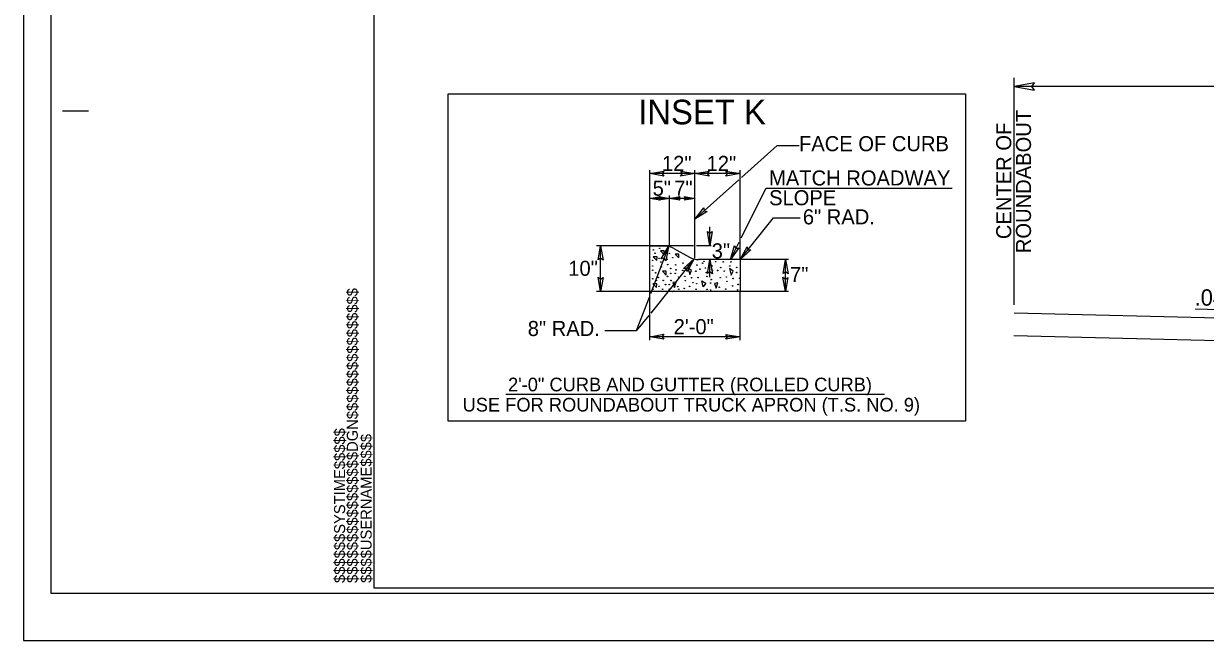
# Model space of a CAD drawing. Extents: x 958711 to 962106, y 831169 to 840840.
# Drawn here: x 958711 to 959274, y 836067 to 836361 of the extents above; entities that cross this region are included whole.
import ezdxf

# ---------------------------------------------------------------- set-up
doc = ezdxf.new("R2010")
doc.units = 0
for name, color, linetype in [('Old_Level_1', 7, 'Continuous'), ('Old_Level_11', 7, 'Continuous'), ('Prop Dimension Text', 7, 'Continuous'), ('Prop Terminator CELL', 7, 'Continuous'), ('Sheet Plot Border Inside CELL', 7, 'Continuous'), ('Sheet Plot Border Outside CELL', 7, 'Continuous'), ('Sheet Typical CELL', 7, 'Continuous'), ('Typical Curb CELL', 7, 'Continuous')]:
    doc.layers.add(name, color=color, linetype=linetype)

msp = doc.modelspace()

# ---------------------------------------------------------------- linework, layer by layer
at = {"layer": 'Old_Level_1'}
for p, q in [((959183.14, 836226.71), (959183.14, 836334.93)), ((959409.36, 836330.79), (959183.14, 836330.79)), ((959053.02, 836287.36), (959070.08, 836302.63)), ((959070.08, 836302.63), (959080.52, 836302.63)), ((959009.31, 836254.84), (959009.31, 836290.83)), ((959030.85, 836248.96), (959030.85, 836290.83)), ((959052.39, 836248.3), (959052.39, 836290.83)), ((959052.39, 836289.22), (959009.31, 836289.22)), ((959030.85, 836267.51), (959051.79, 836286.26)), ((959052.95, 836258.6), (959064.82, 836282.25)), ((959064.82, 836282.25), (959153.53, 836282.25)), ((959018.7, 836277.43), (959009.31, 836277.43)), ((959018.7, 836254.84), (959018.7, 836278.85)), ((959030.85, 836277.43), (959018.7, 836277.43)), ((959052.39, 836248.3), (959068.34, 836268.1)), ((959068.34, 836268.1), (959081.07, 836268.1)), ((959038.01, 836254.84), (959038.01, 836263.83)), ((959047.78, 836248.3), (959051.9, 836256.49)), ((959009.31, 836254.84), (958984, 836254.84)), ((958985.92, 836233.03), (958985.92, 836254.84)), ((959030.17, 836254.84), (959009.31, 836254.84)), ((959018.28, 836254.48), (959009.66, 836231.93)), ((959038.64, 836254.84), (959031.55, 836254.84)), ((959030.56, 836248.54), (959009.79, 836222.78)), ((959038.01, 836239.9), (959038.01, 836248.3)), ((959075.56, 836248.3), (959052.39, 836248.3)), ((959052.39, 836245.6), (959052.39, 836239.13)), ((959074.07, 836233.03), (959074.07, 836248.3)), ((959009.31, 836233.03), (958984, 836233.03)), ((959008.99, 836230.18), (959002.89, 836214.22)), ((959009.31, 836209.88), (959009.31, 836233.03)), ((959052.39, 836209.88), (959052.39, 836233.03)), ((959075.56, 836233.03), (959052.39, 836233.03)), ((959183.14, 836222.88), (959403.98, 836217.36)), ((959269.32, 836224.71), (959300.64, 836224.08)), ((959008.85, 836221.62), (959002.89, 836214.22)), ((959002.89, 836214.22), (958987.87, 836214.22)), ((959052.39, 836211.44), (959009.31, 836211.44)), ((959182.87, 836212.14), (959403.98, 836206.61)), ((958940.77, 836184.02), (959121.19, 836184.02))]:
    msp.add_line(p, q, dxfattribs=at)
msp.add_lwpolyline([(958913.22, 836327.23), (959159.94, 836327.23), (959159.94, 836171.22), (958913.22, 836171.22)], close=True, dxfattribs=at)
at = {"layer": 'Old_Level_11'}
msp.add_lwpolyline([(959192.75, 836332.44), (959183.14, 836330.79), (959192.81, 836329.07), (959191.58, 836330.79)], close=True, dxfattribs=at)
at = {"layer": 'Prop Terminator CELL'}
for points in [[(959016.06, 836288.06), (959009.31, 836289.22), (959016.1, 836290.42), (959015.23, 836289.22)], [(959024.1, 836290.39), (959030.85, 836289.22), (959024.06, 836288.02), (959024.92, 836289.22)], [(959037.6, 836288.06), (959030.85, 836289.22), (959037.64, 836290.42), (959036.77, 836289.22)], [(959045.64, 836290.39), (959052.39, 836289.22), (959045.6, 836288.02), (959046.46, 836289.22)], [(959014.26, 836276.58), (959009.31, 836277.43), (959014.29, 836278.31), (959013.65, 836277.43)], [(959013.75, 836278.29), (959018.7, 836277.43), (959013.73, 836276.55), (959014.36, 836277.43)], [(959023.65, 836276.58), (959018.7, 836277.43), (959023.68, 836278.31), (959023.05, 836277.43)], [(959025.9, 836278.29), (959030.85, 836277.43), (959025.87, 836276.55), (959026.5, 836277.43)], [(959036.65, 836271.15), (959030.85, 836267.51), (959035.1, 836272.93), (959035.26, 836271.46)], [(959039.17, 836261.59), (959038.01, 836254.84), (959036.81, 836261.63), (959038.01, 836260.77)], [(958984.76, 836248.09), (958985.92, 836254.84), (958987.12, 836248.05), (958985.92, 836248.92)], [(959014.78, 836248.59), (959018.28, 836254.48), (959016.98, 836247.71), (959016.16, 836248.94)], [(959051.85, 836253.81), (959047.78, 836248.3), (959049.76, 836254.9), (959050.44, 836253.59)], [(959057.53, 836252.83), (959052.39, 836248.3), (959055.71, 836254.34), (959056.1, 836252.91)], [(959025.41, 836244.02), (959030.56, 836248.54), (959027.23, 836242.51), (959026.84, 836243.93)], [(959036.85, 836241.55), (959038.01, 836248.3), (959039.21, 836241.51), (959038.01, 836242.37)], [(959072.91, 836241.55), (959074.07, 836248.3), (959075.27, 836241.51), (959074.07, 836242.37)], [(958987.08, 836239.78), (958985.92, 836233.03), (958984.72, 836239.82), (958985.92, 836238.96)], [(959075.23, 836239.78), (959074.07, 836233.03), (959072.87, 836239.82), (959074.07, 836238.96)], [(959016.06, 836210.27), (959009.31, 836211.44), (959016.1, 836212.64), (959015.23, 836211.44)], [(959045.64, 836212.6), (959052.39, 836211.44), (959045.6, 836210.24), (959046.46, 836211.44)]]:
    msp.add_lwpolyline(points, close=True, dxfattribs=at)
at = {"layer": 'Sheet Plot Border Inside CELL'}
msp.add_lwpolyline([(960390.3, 837144.29), (958723.8, 837144.29), (958723.8, 836089.19), (960390.3, 836089.19)], close=True, dxfattribs=at)
at = {"layer": 'Sheet Plot Border Outside CELL'}
msp.add_lwpolyline([(960394.8, 837166.74), (958710.8, 837166.74), (958710.8, 836066.74), (960394.8, 836066.74)], close=True, dxfattribs=at)
at = {"layer": 'Sheet Typical CELL'}
for p, q in [((958729.3, 836319.24), (958741.8, 836319.24)), ((958877.8, 836091.74), (958877.8, 836091.74)), ((958877.8, 836091.74), (958877.8, 836091.74)), ((958877.8, 836091.74), (958877.8, 836091.74)), ((958877.8, 836091.74), (958877.8, 836091.74)), ((958877.8, 836091.74), (958877.8, 836091.74)), ((958877.8, 836091.74), (958877.8, 836091.74))]:
    msp.add_line(p, q, dxfattribs=at)
msp.add_lwpolyline([(960377.8, 837141.74), (958877.8, 837141.74), (958877.8, 836091.74), (960377.8, 836091.74)], close=True, dxfattribs=at)
msp.add_lwpolyline([(958915.3, 836091.74), (958915.3, 836091.74)], dxfattribs=at)
at = {"layer": 'Typical Curb CELL'}
for p, q in [((959009.31, 836233.03), (959009.31, 836254.84)), ((959009.31, 836254.84), (959016.69, 836254.66)), ((959016.25, 836252.36), (959014.4, 836252.36)), ((959014.4, 836252.36), (959016.15, 836250.51)), ((959016.15, 836250.51), (959016.25, 836252.36)), ((959020.81, 836253.54), (959028.3, 836249.42)), ((959023.25, 836250.87), (959021.39, 836250.87)), ((959021.39, 836250.87), (959023.14, 836249.02)), ((959023.14, 836249.02), (959023.25, 836250.87)), ((959012.86, 836249.62), (959011.01, 836249.62)), ((959011.01, 836249.62), (959012.76, 836247.76)), ((959012.76, 836247.76), (959012.86, 836249.62)), ((959052.39, 836248.3), (959032.64, 836248.3)), ((959052.39, 836248.3), (959052.39, 836233.03)), ((959017.22, 836242.67), (959015.37, 836242.67)), ((959015.37, 836242.67), (959017.12, 836240.81)), ((959017.12, 836240.81), (959017.22, 836242.67)), ((959027.51, 836244.35), (959028.41, 836241.13)), ((959029.28, 836243.09), (959027.51, 836244.35)), ((959028.41, 836241.13), (959029.28, 836243.09)), ((959047.32, 836244.01), (959048.21, 836240.81)), ((959049.08, 836242.75), (959047.32, 836244.01)), ((959048.21, 836240.81), (959049.08, 836242.75)), ((959012.7, 836236.77), (959010.85, 836236.77)), ((959010.85, 836236.77), (959012.6, 836234.91)), ((959012.6, 836234.91), (959012.7, 836236.77)), ((959021.97, 836237.55), (959020.41, 836237.25)), ((959020.41, 836237.25), (959021.2, 836234.91)), ((959021.2, 836234.91), (959021.97, 836237.55)), ((959034.14, 836238.13), (959036.08, 836237.06)), ((959034.82, 836235.31), (959034.14, 836238.13)), ((959036.08, 836237.06), (959034.82, 836235.31)), ((959041.77, 836237.21), (959040.22, 836236.91)), ((959040.22, 836236.91), (959041.01, 836234.57)), ((959041.01, 836234.57), (959041.77, 836237.21)), ((959052.39, 836233.03), (959009.31, 836233.03))]:
    msp.add_line(p, q, dxfattribs=at)
for centre, radius in [((959011.06, 836252.86), 0.137), ((959011.89, 836251.29), 0.137), ((959014.1, 836253.6), 0.137), ((959018.26, 836253.6), 0.137), ((959018.67, 836251.25), 0.137), ((959010.73, 836247.88), 0.137), ((959010.73, 836245.2), 0.137), ((959013.83, 836248.84), 0.137), ((959014.61, 836247.09), 0.137), ((959017.61, 836248.43), 0.137), ((959017.89, 836245.89), 0.137), ((959020.29, 836249.17), 0.137), ((959021.69, 836245.71), 0.137), ((959025.19, 836246.59), 0.137), ((959027.72, 836245.52), 0.137), ((959031.81, 836245.62), 0.137), ((959034.55, 836246.53), 0.137), ((959035.16, 836247.42), 0.137), ((959038, 836246.76), 0.137), ((959039.07, 836245.23), 0.137), ((959040.74, 836247.28), 0.137), ((959044.37, 836247.14), 0.137), ((959047.52, 836245.18), 0.137), ((959048.05, 836247.14), 0.137), ((959010.73, 836243.17), 0.137), ((959012.17, 836241.92), 0.137), ((959013.41, 836239.7), 0.137), ((959014.8, 836244.74), 0.137), ((959017.79, 836240.21), 0.137), ((959019.32, 836244), 0.137), ((959019.36, 836241.64), 0.137), ((959021.49, 836241.64), 0.137), ((959021.88, 836243.38), 0.137), ((959023.14, 836239.97), 0.137), ((959025.09, 836243.09), 0.137), ((959026.07, 836240.26), 0.137), ((959029.28, 836239.58), 0.137), ((959031.32, 836242.7), 0.137), ((959032.39, 836239.68), 0.137), ((959033.27, 836243.67), 0.137), ((959035.89, 836244.25), 0.137), ((959036.38, 836242.11), 0.137), ((959036.6, 836240.24), 0.137), ((959038.82, 836243.77), 0.137), ((959039.15, 836243.14), 0.137), ((959041.68, 836243.04), 0.137), ((959042.95, 836239.64), 0.137), ((959043.21, 836244.44), 0.137), ((959044.89, 836242.75), 0.137), ((959045.87, 836239.93), 0.137), ((959050.84, 836244.53), 0.137), ((959050.84, 836242.11), 0.137), ((959010.73, 836239.1), 0.137), ((959010.83, 836234.11), 0.137), ((959012.49, 836238.32), 0.137), ((959013.78, 836235.5), 0.137), ((959015.49, 836234.11), 0.137), ((959015.76, 836238.32), 0.137), ((959016.83, 836236.33), 0.137), ((959018.63, 836236.33), 0.137), ((959018.63, 836234.11), 0.137), ((959019.41, 836238.27), 0.137), ((959022.66, 836235.4), 0.137), ((959023.15, 836234.11), 0.137), ((959025.77, 836234.52), 0.137), ((959026.36, 836238.22), 0.137), ((959028.32, 836235.45), 0.137), ((959029.93, 836237.25), 0.137), ((959031.42, 836234.13), 0.137), ((959031.71, 836236.76), 0.137), ((959036.67, 836234.04), 0.137), ((959038.33, 836237.05), 0.137), ((959038.33, 836233.74), 0.137), ((959038.67, 836238.76), 0.137), ((959042.46, 836235.06), 0.137), ((959045.57, 836234.18), 0.137), ((959046.16, 836237.88), 0.137), ((959048.84, 836235.72), 0.137), ((959049.08, 836239.25), 0.137), ((959051.22, 836233.8), 0.137), ((959051.51, 836236.42), 0.137), ((959052.19, 836239.34), 0.137), ((959020.08, 836233.03), 0.0261), ((959052.39, 836233.03), 0.0261)]:
    msp.add_circle(centre, radius, dxfattribs=at)
for centre, radius, start, end in [((959016.47, 836245.66), 9, 61.1507, 88.5679), ((959032.64, 836257.3), 9, 241.1507, 270), ((959020.81, 836233.16), 0.137, 27.0386, 154.2416)]:
    msp.add_arc(centre, radius, start, end, dxfattribs=at)

# ---------------------------------------------------------------- texts
at = {"layer": 'Old_Level_1'}
for s, height, p in [('INSET K', 11.716, (959003.8, 836312.74)), ('FACE OF CURB', 7.1816, (959080.5, 836299.91)), ('12"', 7.182, (959015.16, 836290.5)), ('12"', 7.182, (959036.45, 836290.5)), ('MATCH ROADWAY', 7.1816, (959066.24, 836283.57)), ('5"', 7.182, (959010.71, 836278.69)), ('7"', 7.182, (959021.02, 836278.69)), ('SLOPE', 7.182, (959066.24, 836274.15)), ('6" RAD.', 7.182, (959082.33, 836265.04)), ('3"', 7.182, (959038.89, 836248.82)), ('10"', 7.182, (958970.49, 836240.51)), ('7"', 7.182, (959076.24, 836237.6)), ('8" RAD.', 7.182, (958951.17, 836211.82)), ('2\'-0"', 7.182, (959020.73, 836212.69)), ('2\'-0" CURB AND GUTTER (ROLLED CURB)', 6.5088, (958941.77, 836185.45)), ('USE FOR ROUNDABOUT TRUCK APRON (T.S. NO. 9)', 6.5088, (958920.12, 836175.82))]:
    msp.add_text(s, height=height, dxfattribs=at).set_placement(p)
for s, p in [('ROUNDABOUT', (959191.12, 836251.31)), ('CENTER OF', (959181.71, 836258.01))]:
    msp.add_text(s, height=7.182, rotation=90, dxfattribs=at).set_placement(p)
at = {"layer": 'Prop Dimension Text'}
msp.add_text('.040', height=7.801, rotation=360, dxfattribs=at).set_placement((959269.14, 836226.28))
at = {"layer": 'Sheet Typical CELL'}
for s, p in [('$$$$$$$$$$$$$$$$DGN$$$$$$$$$$$$$$$$', (958870.15, 836094.1)), ('$$$$$$SYSTIME$$$$$', (958864.1, 836094.1)), ('$$$$USERNAME$$$$', (958876.73, 836094.12))]:
    msp.add_text(s, height=5.25, rotation=90, dxfattribs=at).set_placement(p)

doc.saveas('drawing.dxf')
